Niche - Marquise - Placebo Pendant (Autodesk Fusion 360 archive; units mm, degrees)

design "Marquise - Modular" references "Modular - Placebo - Bayonet Connector", "Modular - Placedo - Cord Set"
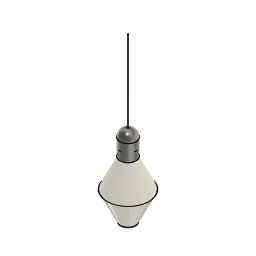
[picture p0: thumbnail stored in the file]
sketch "Sketch1" plane through (0, 0, 0) normal (0, 1, 0) x axis (1, 0, 0)
  line L1 (0, 127) -> (0, -127)
  line L2 (76.2, 127) -> (76.2, -127)
  line L3 (-76.2, 127) -> (-76.2, -127)
  line L4 (127, 0) -> (-127, 0)
  line L5 (127, -101.6) -> (-127, -101.6)
  line L6 (127, 101.6) -> (-127, 101.6)
  line L7 (26.924, 127) -> (26.924, -127)
  line L8 (-26.924, 127) -> (-26.924, -127)
  line L9 (26.924, -101.6) -> (-26.924, -101.6)
  line L10 (26.924, -114.3) -> (-26.924, -114.3)
  line L11 (76.2, 0) -> (26.924, 101.6)
  line L12 (26.924, -101.6) -> (76.2, 0)
  line L13 (-26.924, -101.6) -> (-76.2, 0)
  line L14 (-76.2, 0) -> (-26.924, 101.6)
  point P14 (26.924, -127)
  point P16 (-26.924, -127)
  point P15 (26.924, 127)
  point P17 (-26.924, 127)
  point P18 (-26.924, -101.6)
  point P19 (26.924, -101.6)
  point P22 (26.924, 101.6)
  point P23 (76.2, 0)
  point P25 (-26.924, -101.6)
  point P26 (-26.924, 101.6)
  point P24 (-76.2, 0)
  vertical L1
  perpendicular L1 L4
  symmetric L1 P14 P16
  symmetric L1 P15 P17
  coincident L5 P18
  coincident L8 P18
  coincident L7 P19
  coincident L5 P19
  coincident L7 P22
  coincident L6 P22
  midpoint L2 P23
  symmetric L1 P19 P25
  symmetric L1 P22 P26
  symmetric L1 P23 P24
  dimension "d3" = 101.6
  dimension "d4" = -101.6
  dimension "d6" = 12.7
revolve "Revolve1" sketch "Sketch1" AlongAngle 360 bodies "Marquise Modular"
shell "Shell1" innerThickness 1.905
component_from_bodies "Body->Comp"
component_insert "Component Insert1"
component_insert "Component Insert2"
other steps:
base_feature "Base Feature" bodies "Marquise Modular"
create_component "CreateComponent1"
remove_body "RemoveBody1"
named bodies: "Marquise Modular"

design "Modular - Placebo - Bayonet Connector"
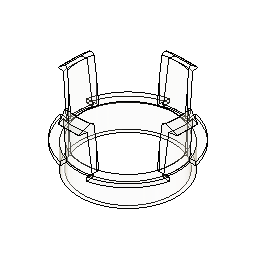
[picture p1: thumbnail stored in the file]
sketch "Sketch1" plane through (0, 0, 0) normal (0, 0, 1) x axis (1, 0, 0)
  circle C1 centre (0, 0) radius 23.241
  point P1 (0, 0)
  point P2 (0, 0)
  coincident P1 P2
  dimension "d1" diameter C1 = 46.482
extrude "Extrude1" new body sketch "Sketch1" along normal blind 11.176
sketch "Sketch2" plane through (0, 0, 11.176) normal (0, 0, 1) x axis (-1, 0, 0)
  line L1 (-23.2795, -6.35) -> (-26.1645, -6.35)
  line L2 (-23.2795, 6.35) -> (-26.1645, 6.35)
  line L3 (26.1645, -6.35) -> (23.2795, -6.35)
  line L4 (26.1645, 6.35) -> (23.2795, 6.35)
  line L5 (6.35, -23.2795) -> (6.35, -26.1645)
  line L6 (-6.35, -23.2795) -> (-6.35, -26.1645)
  line L7 (6.35, 26.1645) -> (6.35, 23.2795)
  line L8 (-6.35, 26.1645) -> (-6.35, 23.2795)
  line L9 (0, -24.13) -> (0, -26.924)
  line L10 (6.35, -23.2795) -> (6.35, -22.3567)
  line L11 (-6.35, -23.2795) -> (-6.35, -22.3567)
  line L12 (23.2795, -6.35) -> (22.3567, -6.35)
  line L13 (23.2795, 6.35) -> (22.3567, 6.35)
  line L14 (-23.2795, 6.35) -> (-22.3567, 6.35)
  line L15 (-23.2795, -6.35) -> (-22.3567, -6.35)
  line L16 (6.35, 22.3567) -> (6.35, 23.2795)
  line L17 (-6.35, 22.3567) -> (-6.35, 23.2795)
  circle C1 centre (0, 0) radius 23.241
  arc A1 centre (0, 0) radius 26.924 clockwise from (-6.35, -26.1645) to (-26.1645, -6.35)
  arc A2 centre (0, 0) radius 26.924 clockwise from (26.1645, -6.35) to (6.35, -26.1645)
  arc A3 centre (0, 0) radius 24.13 clockwise from (23.2795, 6.35) to (23.2795, -6.35)
  arc A4 centre (0, 0) radius 24.13 clockwise from (6.35, -23.2795) to (-6.35, -23.2795)
  arc A5 centre (0, 0) radius 26.924 clockwise from (6.35, 26.1645) to (26.1645, 6.35)
  arc A6 centre (0, 0) radius 26.924 clockwise from (-26.1645, 6.35) to (-6.35, 26.1645)
  arc A7 centre (0, 0) radius 24.13 clockwise from (-6.35, 23.2795) to (6.35, 23.2795)
  arc A8 centre (0, 0) radius 24.13 clockwise from (-23.2795, -6.35) to (-23.2795, 6.35)
  point P2 (0, 0)
  point P4 (0, 0)
  point P12 (-23.2795, -6.35)
  point P13 (-22.3567, -6.35)
  point P14 (-23.2795, 6.35)
  point P15 (-22.3567, 6.35)
  point P16 (22.3567, -6.35)
  point P18 (22.3567, 6.35)
  point P24 (6.35, 23.2795)
  point P28 (6.35, -22.3567)
  point P29 (-6.35, -22.3567)
  point P31 (-6.35, 26.1645)
  point P35 (0, -24.13)
  point P36 (6.35, 22.3567)
  point P37 (-6.35, 22.3567)
  coincident P2 P4
  vertical L9
  concentric A2 A3
  concentric A1 A2
  coincident P12 A3
  coincident C1 P13
  coincident P14 A3
  coincident C1 P15
  coincident C1 P16
  coincident C1 P18
  concentric A2 A5
  coincident P24 L5
  concentric A3 A7
  concentric A4 A7
  coincident C1 P28
  coincident C1 P29
  coincident P31 A5
  concentric A5 A6
  concentric A7 A8
  coincident A4 P35
  horizontal L12
  coincident C1 P36
  parallel L7 L16
  coincident C1 P37
  parallel L8 L17
  dimension "d4" diameter A2 = 53.848
extrude "Extrude2" add sketch "Sketch2" profile of C1 A8 L10 L11 L12 L13 L14 L15 L16 L17 along normal blind 0.762
extrude "Extrude3" add sketch "Sketch2" profile of C1 A6 L7 L8 L4 L3 L10 L11 L12 L13 L14 L15 L16 L17 along normal blind 1.7018
extrude "Extrude4" add sketch "Sketch2" profile of C1 along normal blind 1.7018
work_plane "WorkPlane1" AlongDistance 33.8963
sketch "Sketch3" plane through (0, 0, 33.8963) normal (0, 0, 1) x axis (1, 0, 0)
  line L1 (0, 20.3925) -> (0, 27.5045)
  line L2 (-6.604, 20.3925) -> (-6.604, 27.5045)
  line L3 (6.604, 20.3925) -> (6.604, 27.5045)
  circle C1 centre (0, 0) radius 23.7363
  circle C2 centre (0, 0) radius 27.305
  arc A1 centre (0.0021, 0.2001) radius 23.9364 clockwise from (-6.604, 23.2068) to (6.604, 23.208)
  arc A2 centre (0.0021, 0.2001) radius 21.3964 clockwise from (-6.604, 20.5511) to (6.604, 20.5525)
  point P1 (0, 0)
  point P2 (0, 0)
  point P6 (-6.604, 27.5045)
  point P8 (6.604, 27.5045)
  point P7 (-6.604, 20.3925)
  point P9 (6.604, 20.3925)
  point P11 (-6.604, 23.2068)
  point P12 (6.604, 23.208)
  point P14 (-6.604, 20.5511)
  point P15 (6.604, 20.5525)
  coincident P1 P2
  concentric C1 C2
  vertical L1
  symmetric L1 P6 P8
  symmetric L1 P7 P9
  tangent C1 A1
  coincident L2 P11
  coincident L3 P12
  concentric A1 A2
  coincident L2 P14
  coincident L3 P15
  dimension "d14" diameter C1 = 47.4726
  dimension "d15" diameter C2 = 54.61
  dimension "d16" = 6.604
extrude "Extrude5" new body sketch "Sketch3" profile of C1 L1 L2 L3 A1 A2 against normal blind 21.59
sketch "Sketch4" plane through (0, 0, 33.8963) normal (0, 0, 1) x axis (-1, 0, 0)
  line L1 (6.604, -20.5511) -> (6.604, -23.2068)
  line L2 (-6.604, -23.208) -> (-6.604, -20.5525)
  line L3 (-5.08, -26.67) -> (-6.604, -20.5525)
  line L4 (5.08, -26.67) -> (-5.08, -26.67)
  line L5 (6.604, -20.5511) -> (5.08, -26.67)
  arc A1 centre (-0.0021, -0.2001) radius 23.9364 clockwise from (6.604, -23.2068) to (-6.604, -23.208)
  arc A2 centre (-0.0021, -0.2001) radius 21.3964 clockwise from (6.604, -20.5511) to (-6.604, -20.5525)
  point P6 (-6.604, -20.5525)
  point P7 (-6.604, -20.5525)
  point P5 (6.604, -20.5511)
  point P10 (6.604, -20.5511)
  coincident P6 P7
  perpendicular L2 L4
  coincident P5 P10
extrude "Extrude6" add sketch "Sketch4" profile of A1 A2 L3 L4 L5 against normal blind 3.175
move "Move1"
sketch "Sketch5" plane through (0, 3.4565, 35.8974) normal (0, 0.0958, 0.9954) x axis (-1, 0, 0)
  line L1 (6.604, -19.277) -> (6.604, -21.9327)
  line L2 (-6.604, -21.9339) -> (-6.604, -19.2784)
  line L3 (-5.08, -25.3959) -> (-5.8947, -22.1257)
  line L4 (5.08, -25.3959) -> (-5.08, -25.3959)
  line L5 (5.8948, -22.1246) -> (5.08, -25.3959)
  line L6 (-8.1218, -17.3223) -> (-6.0831, -25.506)
  line L7 (-0.004, -17.3223) -> (-0.0002, -17.3223)
  line L8 (-8.1218, -17.3223) -> (-6.8295, -17.3223)
  line L9 (0, -25.3959) -> (0.0001, -20.3223)
  line L10 (-6.8295, -17.3223) -> (-4.7917, -25.5025)
  line L11 (8.1222, -17.3227) -> (6.0831, -25.5062)
  line L12 (8.1222, -17.3227) -> (6.8299, -17.3226)
  line L13 (-4.7917, -25.5025) -> (-6.1096, -25.506)
  line L14 (4.7917, -25.5027) -> (6.0831, -25.5062)
  line L15 (6.8299, -17.3226) -> (4.7917, -25.5027)
  arc A1 centre (-0.0021, 1.074) radius 23.9364 clockwise from (6.604, -21.9327) to (5.8948, -22.1246)
  arc A2 centre (-0.0021, 1.074) radius 21.3964 clockwise from (6.604, -19.277) to (-6.604, -19.2784)
  arc A3 centre (-0.0021, 1.074) radius 23.9364 clockwise from (-5.8947, -22.1257) to (-6.604, -21.9339)
  arc A4 centre (-0.0021, 1.074) radius 18.3964 clockwise from (5.6778, -16.4236) to (-5.6783, -16.4247)
  point P14 (-0.0002, -17.3223)
  point P15 (-8.1218, -17.3223)
  point P16 (-0.004, -17.3223)
  point P17 (0.0001, -20.3223)
  point P18 (0, -25.3959)
  point P20 (8.1222, -17.3227)
  point P19 (-6.8295, -17.3223)
  point P21 (6.8299, -17.3226)
  point P23 (-6.0831, -25.506)
  point P26 (6.8299, -17.3226)
  point P24 (-4.7917, -25.5025)
  point P25 (4.7917, -25.5027)
  midpoint A4 P14
  horizontal L7
  coincident P15 L7
  coincident A4 P16
  collinear L7 L8
  midpoint A2 P17
  midpoint L4 P18
  symmetric P15 L9 P20
  symmetric L9 P19 P21
  coincident L13 P23
  symmetric L9 P19 P26
  symmetric L9 P24 P25
  dimension "d22" = -3
extrude "Extrude7" cut sketch "Sketch5" profile of A1 L1 A2 L2 A3 L3 L4 L5 L8 L6 L10 L11 L12 L13 L14 L15 against normal blind 25.146 taper -1.45
remove_body "RemoveBody1"
remove_body "RemoveBody2"
chamfer "Chamfer1" sketch "Sketch4" distance 4.572 distance 3.048
circular_pattern "C-Pattern1" TotalAngle 360
extrude "Extrude8" add sketch "Sketch4" along a picked direction blind 0.508
extrude "Extrude9" add of existing geometry blind 0.508
extrude "Extrude10" add of existing geometry blind 0.508
extrude "Extrude11" add of existing geometry blind 0.508
hole "Hole1" sketch "Sketch4" HoleDepth 38.1 HoleDiameter 42.926 TipAngle 118
fillet "Fillet1" sketch "Sketch4" radius 1.27

design "Modular - Placedo - Cord Set"
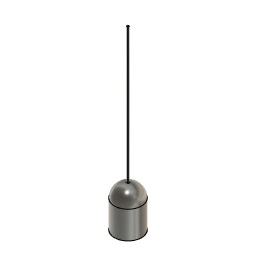
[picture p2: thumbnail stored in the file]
sketch "Sketch1" plane through (0, 0, 0) normal (0, 1, 0) x axis (1, 0, 0)
  line L1 (0, -88.9) -> (0, 0)
  line L2 (-29.5402, -88.9) -> (-29.5402, 0)
  line L3 (29.5402, -88.9) -> (29.5402, 0)
  line L4 (29.5402, 8.5598) -> (29.5402, -59.3598)
  line L5 (-29.5402, -59.3598) -> (-29.5402, 8.5598)
  line L6 (0, 38.1) -> (0, -88.9)
  line L7 (29.5402, 0) -> (-29.5402, 0)
  arc A1 centre (0, 8.5598) radius 29.5402 clockwise from (-29.5402, 8.5598) to (29.5402, 8.5598)
  arc A2 centre (0, -59.3598) radius 29.5402 clockwise from (29.5402, -59.3598) to (-29.5402, -59.3598)
  point P1 (0, 0)
  point P2 (0, 0)
  point P4 (-29.5402, 0)
  point P6 (29.5402, 0)
  point P5 (-29.5402, -88.9)
  point P7 (29.5402, -88.9)
  point P3 (0, -88.9)
  point P14 (0, 38.1)
  coincident P1 P2
  vertical L1
  symmetric L1 P4 P6
  symmetric L1 P5 P7
  tangent L4 A1
  tangent A1 L5
  parallel L4 L5
  tangent L5 A2
  tangent L4 A2
  midpoint P3 A2
  midpoint A1 P14
  parallel L1 L6
  dimension "d1" = 29.5402
revolve "Revolve1" sketch "Sketch1" AlongAngle 360
shell "Shell1" innerThickness 1.524
sketch "Sketch2" plane through (0, 0, 0) normal (0, 0, 1) x axis (1, 0, 0)
  circle C1 centre (0, 0) radius 2.8575
  point P1 (0, 0)
  point P2 (0, 0)
  coincident P1 P2
  dimension "d4" diameter C1 = 5.715
extrude "Extrude1" cut sketch "Sketch2" along normal blind 101.6
sketch "Sketch3" plane through (0, 0, 0) normal (0, 0, 1) x axis (1, 0, 0)
  circle C1 centre (0, 0) radius 2.286
  point P1 (0, 0)
  point P2 (0, 0)
  coincident P1 P2
  dimension "d7" diameter C1 = 4.572
extrude "Extrude2" new body sketch "Sketch3" along normal blind 304.8
move "Move1"
sketch "Sketch4" plane through (0, 0, 0) normal (0, 0, 1) x axis (1, 0, 0)
  circle C1 centre (0, 0) radius 18.796
  point P1 (0, 0)
  point P2 (0, 0)
  coincident P1 P2
  dimension "d10" diameter C1 = 37.592
extrude "Extrude3" new body sketch "Sketch4" along normal blind 31.75
move "Move2"
offset_faces "OffsetFaces1" distance 38.1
